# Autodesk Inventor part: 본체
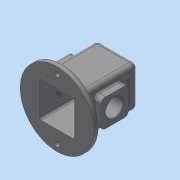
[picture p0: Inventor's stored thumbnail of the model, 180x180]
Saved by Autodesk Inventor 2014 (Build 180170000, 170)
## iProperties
Created: 2021-08
Part Number: 본체
Material: 일반
Document SubType Name: Modeling
Designer: dg
Density: 1 g/cm^3
Appearance: 기본값
Author: dg
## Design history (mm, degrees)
sketch "스케치1"
  geometry: L1 (37, -37)-(-37, -37); L2 (-37, -37)-(-37, 37); L3 (-37, 37)-(37, 37); L4 (37, 37)-(37, -37); 3 further points
  constraints: 8 end point, 2 midpoint, 2 parallel, 1 horizontal, 1 horizontal alignment, 1 perpendicular, 1 vertical alignment
  dimensions: "d0" = 74 distance of L1.start L1.end; "d1" = 74 distance of L1.end L2.end
extrude "돌출1" new body sketch "스케치1" distance "d2" = 100; taper "d3" = 0 deg
sketch "스케치2"
  geometry: C1 r 67 at (0, 0); 1 further point
  constraints: 1 centre point, 1 coincident
  dimensions: "d4" = 134 diameter of C1
extrude "돌출2" join sketch "스케치2" distance "d5" = 10; taper "d6" = 0 deg
sketch "스케치3"
  geometry: L1 (-32, 32)-(32, 32); L2 (32, 32)-(32, -32); L3 (32, -32)-(-32, -32); L4 (-32, -32)-(-32, 32); L5 (37, 37)-(-37, 37) reference; C1 r 67 at (0, 0) reference; 2 further points
  constraints: 8 end point, 2 midpoint, 2 parallel, 1 horizontal, 1 horizontal alignment, 1 perpendicular, 1 vertical alignment
  dimensions: "d7" = 64 distance of L1.start L1.end; "d8" = 64 distance of L1.end L2.end
extrude "돌출3" cut sketch "스케치3" distance "d9" = 105; taper "d10" = 0 deg
sketch "스케치4"
  geometry: L1 (100, 37)-(100, -37) reference; L2 (100, 0)-(110, 0); L3 (110, 0)-(110, 20); L4 (110, 20)-(100, 21.051); L5 (0, 37)-(100, 37) reference; L6 (100, 21.051)-(100, 0); 1 further point
  constraints: 8 end point, 3 perpendicular, 1 midpoint, 1 point on line
  dimensions: "d11" = 10 distance of L2.start L2.end; "d12" = 20 distance of L2.end L3.end; "d13" = 6 deg angle of L4 L5
revolve "회전1" sketch "스케치4" stored, may be unused: angle "d14" = 90 deg
hole "구멍1" diameter "d17" = 21; stored, may be unused: countersink angle "d21" = 90 deg, drill point angle "d23" = 118 deg; dims "d15" = 10, "d16" = 10, "d18" = 6, "d19" = 28, "d20" = 4, "d22" = 50
sketch "스케치5"
  geometry: L1 (74, -100)-(0, -100) reference; L2 (12, -30)-(62, -30); L3 (62, -30)-(62, -80); L4 (62, -80)-(12, -80); L5 (12, -80)-(12, -30); L6 (-30, -110)-(104, -110) reference; 4 further points
  constraints: 8 end point, 3 midpoint, 2 parallel, 1 horizontal, 1 perpendicular, 1 vertical alignment
  dimensions: "d24" = 50 distance of L2.start L2.end; "d25" = 50 distance of L4.end L2.start; "d26" = 55 distance from line of L6 point (62, -55)
extrude "돌출4" join sketch "스케치5" distance "d27" = 13; taper "d28" = 0 deg
sketch "스케치6"
  geometry: L1 (-32, -10)-(-32, 95) reference; L2 (-32, 45)-(-25, 45); L3 (32, -10)-(-32, -10) reference; L4 (-32, 45)-(-32, 70); L5 (-25, 45)-(-25, 67.452); L6 (-25, 67.452)-(-32, 70); 1 further point
  constraints: 8 end point, 2 point on line, 1 parallel, 1 perpendicular
  dimensions: "d29" = 7 distance of L2.start L2.end; "d30" = 55 distance between parallel lines of L2 L3; "d31" = 25 distance of L2.start L4.end; "d32" = 110 deg angle of L6 L1
revolve "회전2" sketch "스케치6" stored, may be unused: angle "d33" = 90 deg
sketch "스케치7"
  geometry: L1 (0, 50)-(50, 50) reference; L2 (50, 50)-(50, 0) reference; 4 further points
  constraints: 2 midpoint, 1 horizontal alignment, 1 vertical alignment
hole "구멍2" sketch "스케치7" at (25, 25) diameter "d34" = 32; stored, may be unused: countersink angle "d38" = 90 deg, drill point angle "d40" = 118 deg; dims "d35" = 6, "d36" = 28, "d37" = 4, "d39" = 100
fillet "모깎기1" dims "d41" = 8
fillet "모깎기2" dims "d42" = 8
fillet "모깎기3" dims "d43" = 3
fillet "모깎기4" dims "d44" = 3
chamfer "모따기1" distance "d45" = 1; stored, may be unused: second distance "d46" = 2, angle "d47" = 45 deg
fillet "모깎기5" dims "d48" = 8
fillet "모깎기6" dims "d49" = 3
fillet "모깎기7" dims "d50" = 3
sketch "스케치8"
  geometry: L1 (-8, 92)-(-8, 0) reference; L2 (49, 110)-(9, 110) reference; 2 further points
  constraints: 1 other
  dimensions: "d51" = 37 distance from line of L1 point (29, 82); "d52" = 28 distance from line of point (29, 82) L2
feature "엠보싱1" sketch "스케치8" dims "d0" = 74, "d1" = 74, "d53" = 0.5, "d54" = 0
fillet "모깎기8" dims "d55" = 3
fillet "모깎기9" dims "d56" = 3
sketch "스케치9"
  geometry: C1 r 64 at (0, 0) reference; 1 further point
  constraints: 1 vertical alignment
  dimensions: "d57" = 55 distance of point (0, -55) C1.centre
hole "구멍3" sketch "스케치9" at (0, -55) diameter "d58" = 9; stored, may be unused: countersink angle "d62" = 90 deg, drill point angle "d64" = 118 deg; dims "d59" = 6, "d60" = 28, "d61" = 4, "d63" = 100
hole "구멍4" diameter "d70" = 3.242; stored, may be unused: countersink angle "d74" = 90 deg, drill point angle "d76" = 118 deg; dims "d71" = 8, "d72" = 28, "d73" = 4, "d75" = 10, "d83" = 10, "d84" = 10
node "솔리드1"
mirror "대칭1"
mirror "대칭2"
pattern_circular "원형 패턴1" dims angle "d66" = 360 deg
pattern_linear "직사각형 패턴1" dims "d79" = 34
pattern_linear "직사각형 패턴2" dims "d82" = 34
mirror "대칭3"
